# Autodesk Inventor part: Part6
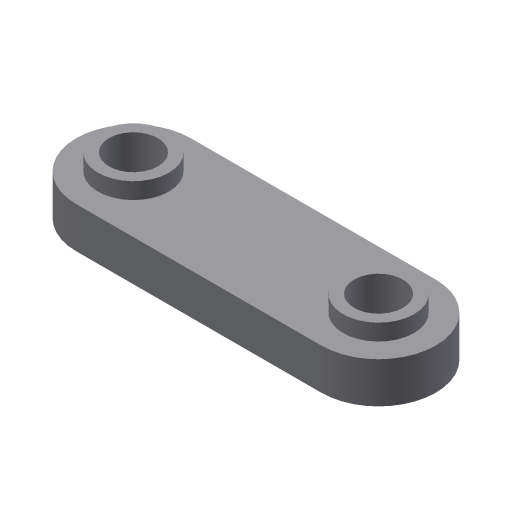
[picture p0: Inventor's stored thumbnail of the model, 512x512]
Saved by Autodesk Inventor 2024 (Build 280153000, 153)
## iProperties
Shininess: 77.0
Length Units: 11269
Angle Units: 11279
Time Units: 11290
Mass Units: 11283
Length Display Precision: 3
Angle Display Precision: 2
Created: 2002-01
Part Number: Part6
Document SubType Name: Modeling
Designer: ***
Density: 1 g/cm^3
Mass: 21.6911 g
Surface Area: 77.1136 cm^2
Volume: 21.6911 cm^3
Material: Generic
Appearance: Default
Density: 0.0
Volumn: 0.0
Area: 0.0
PropertySet Name: Model Information
Control State: 0
Master: False
Checked Out: False
Author: ***
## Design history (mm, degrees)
sketch "Sketch1"
  geometry: L1 (-33.118, 12.346)-(26.882, 12.361); L2 (-33.111, -15.654)-(26.889, -15.639); C1 r 6 at (-33.114, -1.654); C2 r 6 at (26.886, -1.639); A1 r 14 centre (-33.114, -1.654) between (-33.118, 12.346) and (-33.111, -15.654); A2 r 14 centre (26.886, -1.639) between (26.889, -15.639) and (26.882, 12.361)
  constraints: 4 centre point, 4 end point, 4 point on circle, 4 tangent, 2 coincident, 2 equal radius
  dimensions: "d0" = 60 distance of L1.start L1.end; "d1" = 14 radius of A1; "d2" = 12 diameter of C1
extrude "Extrusion1" new body sketch "Sketch1" distance "d3" = 10; taper "d4" = 0 deg
sketch "Sketch2"
  geometry: C1 r 6 at (26.886, -1.639) reference; C2 r 6 at (-33.114, -1.654) reference; C3 r 8.694 at (-33.114, -1.654); C4 r 8.694 at (26.886, -1.639)
  constraints: 2 centre point, 2 coincident, 1 equal radius
extrude "Extrusion2" join sketch "Sketch2" distance "d5" = 4; taper "d6" = 0 deg
body "Solid1"
